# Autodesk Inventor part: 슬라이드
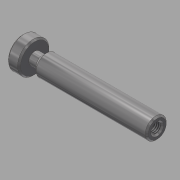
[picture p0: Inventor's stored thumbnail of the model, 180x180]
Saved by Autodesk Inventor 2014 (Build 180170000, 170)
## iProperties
Created: 2015-12
Part Number: 슬라이드
Document SubType Name: Modeling
Designer: mdu
Density: 7.87 g/cm^3
Material: 강철, 탄소
Appearance: 반연마
Mass: 111.518 g
Surface Area: 49.8963 cm^2
Volume: 14.17 cm^3
Author: mdu
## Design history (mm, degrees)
sketch "스케치1"
  geometry: L1 (-45, 0)-(45, 0); L2 (-45, 0)-(-45, 10.5); L3 (-45, 10.5)-(-37, 10.5); L4 (-37, 10.5)-(-37, 4); L5 (-37, 4)-(-32, 4); L6 (-32, 4)-(-29, 7); L7 (-29, 7)-(45, 7); L8 (45, 7)-(45, 0); 2 further points
  constraints: 16 end point, 4 parallel, 2 perpendicular, 1 coincident, 1 horizontal, 1 midpoint
  dimensions: "d0" = 90 distance of L1.start L1.end; "d1" = 21 diameter of L3 L1; "d2" = 14 diameter of L7 L1; "d3" = 8 diameter of L5 L1; "d4" = 8 distance of L2.end L3.end; "d5" = 5 distance of L4.end L5.end; "d6" = 135 deg angle of L6 L5
revolve "회전1" sketch "스케치1" stored, may be unused: angle "d7" = 90 deg
chamfer "모따기1" distance "d8" = 1; stored, may be unused: second distance "d9" = 2, angle "d10" = 45 deg
hole "구멍1" diameter "d13" = 6.647; stored, may be unused: countersink angle "d17" = 90 deg, drill point angle "d19" = 118 deg; dims "d11" = 10, "d12" = 10, "d14" = 9, "d15" = 4, "d16" = 2, "d18" = 12
chamfer "모따기2" distance "d20" = 1; stored, may be unused: second distance "d21" = 2, angle "d22" = 45 deg
node "솔리드1"
